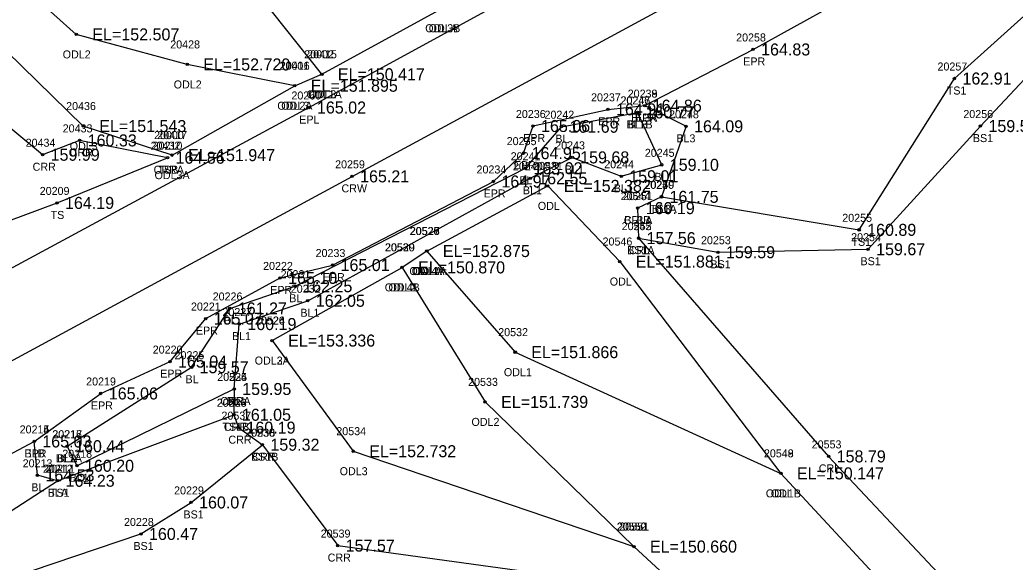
# Model space of a CAD drawing. Extents: x 2279528 to 2280976, y 1061373 to 1062235.
# Drawn here: x 2280192.7 to 2280317.1, y 1061750.3 to 1061818 of the extents above; entities that cross this region are included whole.
import ezdxf

# ---------------------------------------------------------------- set-up
doc = ezdxf.new("R2010")
doc.units = 0
for name, color, linetype in [('RD_DTM_BkLn1', 7, 'Continuous'), ('RD_DTM_BkLn2', 7, 'Continuous'), ('RD_DTM_BkLn_txCode', 7, 'Continuous'), ('RD_EX_H2O', 7, 'Continuous'), ('RD_EX_H2O_txCode', 7, 'Continuous'), ('RD_EX_Road', 7, 'Continuous'), ('RD_EX_Road_txCode', 7, 'Continuous'), ('RD_EX_TX_H2O_ELEV', 7, 'Continuous'), ('RD_EX_TX_Misc_ELEV', 7, 'Continuous'), ('RD_EX_TX_Road_ELEV', 7, 'Continuous'), ('RD_HC_Survey_ELEV', 7, 'Continuous'), ('RD_HC_Survey_txCode', 7, 'Continuous'), ('RD_SMD_Locator', 7, 'Continuous')]:
    doc.layers.add(name, color=color, linetype=linetype)

msp = doc.modelspace()

# ---------------------------------------------------------------- linework, layer by layer
at = {"layer": 'RD_DTM_BkLn1'}
for points in [[(2279559.79, 1061433.13), (2279641.23, 1061477.49), (2279727.93, 1061524.84), (2279814.76, 1061571.75), (2279901.26, 1061618.64), (2279982.8, 1061662.56), (2280064.7, 1061706.86), (2280148.08, 1061751.86), (2280234.22, 1061798.46), (2280310.96, 1061840.01), (2280397.69, 1061887.57), (2280487.27, 1061936.5), (2280573.03, 1061983.12), (2280654.64, 1062027.66), (2280741.28, 1062074.45), (2280833.39, 1062123.87), (2280892.52, 1062155.9), (2280939.46, 1062181.85)], [(2280198.61, 1061764.75), (2280214.16, 1061774.62), (2280218.94, 1061781.96), (2280227.12, 1061784.74), (2280255.88, 1061799.47), (2280260.38, 1061804.66), (2280269.89, 1061806.45)], [(2280198.61, 1061764.75), (2280199.84, 1061762.31), (2280219.49, 1061771.9), (2280220.13, 1061780.01), (2280228.68, 1061782.92), (2280256.48, 1061798.22), (2280261.72, 1061800.83), (2280267.85, 1061798.47), (2280272.92, 1061799.9), (2280269.89, 1061806.45)], [(2280270.78, 1061807.29), (2280275.95, 1061804.71), (2280272.88, 1061795.9), (2280269.9, 1061794.49)], [(2280197.42, 1061760.44), (2280194.9, 1061761.12), (2280194.51, 1061765.35)]]:
    msp.add_lwpolyline(points, dxfattribs=at)
at = {"layer": 'RD_DTM_BkLn2'}
for points in [[(2280272.88, 1061795.9), (2280297.58, 1061791.78), (2280309.49, 1061810.68), (2280320.64, 1061820.76), (2280406.65, 1061872.9), (2280496.79, 1061919.98), (2280582.43, 1061964.41), (2280663.95, 1062011.32), (2280685.25, 1062021.45), (2280750.74, 1062056.04), (2280766.13, 1062062.47), (2280799.22, 1062079.83)], [(2280270.02, 1061790.74), (2280279.94, 1061788.98), (2280298.7, 1061789.36), (2280312.74, 1061804.74), (2280323.13, 1061815.81), (2280411.42, 1061866.03), (2280499.93, 1061915.08), (2280584.56, 1061957.49), (2280666.91, 1062006.18), (2280674.46, 1062011.72), (2280685.18, 1062009.25), (2280689.93, 1062011.32), (2280693.25, 1062019.83), (2280753.26, 1062052.49), (2280766.38, 1062057.83), (2280800.29, 1062072.08)], [(2279918.28, 1061645.97), (2279973.97, 1061675.02), (2280055.41, 1061723.24), (2280139.04, 1061770.27), (2280166.79, 1061783.8), (2280197.35, 1061795.14), (2280211.16, 1061800.79)], [(2280059.22, 1061681.62), (2280071.78, 1061691.76), (2280158.6, 1061733.81), (2280171.38, 1061740.74), (2280178.6, 1061748.25), (2280197.42, 1061760.44), (2280219.45, 1061768.68)], [(2280066.92, 1061680.28), (2280073.37, 1061687.57), (2280161.47, 1061729), (2280173.75, 1061738.9), (2280180.46, 1061744.56), (2280207.84, 1061753.79), (2280214.1, 1061757.73), (2280223.01, 1061764.94)]]:
    msp.add_lwpolyline(points, dxfattribs=at)
at = {"layer": 'RD_EX_H2O'}
for p, q in [((2280230.44, 1061811.21), (2280221.09, 1061822.97)), ((2280243.56, 1061789.13), (2280240.46, 1061787.09))]:
    msp.add_line(p, q, dxfattribs=at)
for points in [[(2280211.16, 1061800.79), (2280200.18, 1061802.95), (2280195.55, 1061801.16), (2280185.62, 1061809.36), (2280166.4, 1061839.27), (2280165.19, 1061847.77), (2280176.13, 1061895.97), (2280173.38, 1061913.11), (2280146.96, 1061940.88), (2280090.97, 1061964.76), (2280049.27, 1062002.4), (2280058.65, 1062048.88), (2280050.78, 1062064.28), (2280035.9, 1062083.09), (2280001.73, 1062095.49), (2279975.65, 1062129.45), (2279976.82, 1062173.44)], [(2280211.72, 1061801.11), (2280200.63, 1061804.74), (2280175.61, 1061829.17), (2280168.33, 1061843.42)], [(2280227.06, 1061809.78), (2280213.62, 1061812.44), (2280199.76, 1061816.19), (2280185.73, 1061828.72), (2280168.33, 1061843.42)], [(2280211.72, 1061801.11), (2280227.06, 1061809.78), (2280230.44, 1061811.21), (2280245.52, 1061819.46)], [(2280243.56, 1061789.13), (2280258.67, 1061797.27), (2280267.66, 1061787.82), (2280287.8, 1061761.36), (2280315.22, 1061731.8), (2280327.48, 1061683.93), (2280307.76, 1061678.04), (2280294.04, 1061661.65), (2280295.74, 1061631.81), (2280310.81, 1061587.94), (2280304.48, 1061546.39), (2280272.84, 1061527.93), (2280259.98, 1061540.36), (2280245.21, 1061537.05), (2280265.99, 1061500.75), (2280299.66, 1061476.28), (2280353.73, 1061471.3), (2280375.17, 1061457.42), (2280376.85, 1061433.19), (2280358.1, 1061419.49), (2280333.32, 1061393.34)], [(2280269.9, 1061794.49), (2280270.02, 1061790.74), (2280293.77, 1061763.48), (2280320.49, 1061735.05), (2280335.4, 1061680.01), (2280309.48, 1061674.63), (2280300.03, 1061660.41), (2280304.47, 1061633.12), (2280315.65, 1061587.64), (2280305.89, 1061543.57), (2280270.77, 1061524.54), (2280257.61, 1061536.28), (2280249.22, 1061535.26), (2280269.33, 1061502.83), (2280301.34, 1061480.02), (2280355.94, 1061475.37), (2280377.91, 1061459.94), (2280379.03, 1061433), (2280360.13, 1061417.18), (2280333.79, 1061387.95)], [(2280243.56, 1061789.13), (2280254.6, 1061776.5), (2280287.8, 1061761.36)], [(2280224.23, 1061777.95), (2280240.46, 1061787.09), (2280250.84, 1061770.29), (2280269.44, 1061752.22)], [(2280224.23, 1061777.95), (2280234.36, 1061764.13), (2280269.44, 1061752.22)], [(2280219.49, 1061771.9), (2280219.45, 1061768.68), (2280220.02, 1061767.07), (2280223.01, 1061764.94), (2280232.42, 1061752.34), (2280266.07, 1061747.74), (2280284.73, 1061725.48), (2280294.86, 1061698.39), (2280278.35, 1061688.54), (2280267.33, 1061659.35), (2280270.69, 1061629.09), (2280284.25, 1061605.42), (2280287.8, 1061578.54), (2280274.54, 1061562.25), (2280261.24, 1061561.71), (2280231.85, 1061561.45), (2280221.24, 1061537.21), (2280230.8, 1061514.2), (2280261.74, 1061476.46), (2280301.47, 1061455.38), (2280325.75, 1061454.26), (2280345.44, 1061445.29), (2280345.67, 1061436.49), (2280313.46, 1061411.55)], [(2280269.44, 1061752.22), (2280294.62, 1061728.95), (2280307.92, 1061693.91), (2280286.99, 1061684.11), (2280274.68, 1061657.45), (2280275.58, 1061630.25), (2280288.86, 1061608.44), (2280293.72, 1061581.7), (2280282.36, 1061552.42), (2280261.54, 1061554.57), (2280239.33, 1061554.65), (2280227, 1061538.36), (2280233.84, 1061514.57), (2280265.76, 1061478.91), (2280302.98, 1061460.15), (2280326.03, 1061460.1), (2280352.94, 1061451.17), (2280354.09, 1061431.94), (2280317.15, 1061398.72)]]:
    msp.add_lwpolyline(points, dxfattribs=at)
at = {"layer": 'RD_EX_Road'}
for points in [[(2279554.31, 1061441.46), (2279636.61, 1061486.51), (2279673.46, 1061506.76), (2279683.06, 1061512.21), (2279723.14, 1061533.54), (2279809.28, 1061580.29), (2279896.91, 1061627.91), (2279977.07, 1061671.02), (2280059.64, 1061715.57), (2280142.91, 1061760.72), (2280228.83, 1061807.06), (2280306.04, 1061849.18), (2280392.98, 1061896.71), (2280482.82, 1061945.75), (2280567.83, 1061991.78), (2280649.94, 1062036.55), (2280660.56, 1062042.19), (2280676.12, 1062050.66), (2280737.28, 1062083.64), (2280828.54, 1062132.77), (2280887.86, 1062164.61), (2280934.91, 1062190.9)], [(2279906, 1061609.76), (2279987.33, 1061653.65), (2280069.09, 1061697.76), (2280153.19, 1061743.35), (2280194.51, 1061765.35), (2280202.82, 1061771.34), (2280211.47, 1061775.32), (2280215.93, 1061780.7), (2280225.22, 1061785.77), (2280231.78, 1061787.38), (2280251.88, 1061797.82), (2280255.66, 1061801.36), (2280256.83, 1061804.75), (2280266.2, 1061806.83), (2280270.78, 1061807.29), (2280284.33, 1061814.31), (2280315.09, 1061831.32), (2280403.05, 1061879.04), (2280492, 1061927.92)]]:
    msp.add_lwpolyline(points, dxfattribs=at)
at = {"layer": 'RD_SMD_Locator'}
for centre in [(2280199.76, 1061816.19), (2280284.33, 1061814.31), (2280213.62, 1061812.44), (2280230.44, 1061811.21), (2280230.44, 1061811.21), (2280227.06, 1061809.78), (2280227.06, 1061809.78), (2280309.49, 1061810.68), (2280270.78, 1061807.29), (2280270.78, 1061807.29), (2280228.83, 1061807.06), (2280266.2, 1061806.83), (2280269.89, 1061806.45), (2280269.89, 1061806.45), (2280200.63, 1061804.74), (2280256.83, 1061804.75), (2280312.74, 1061804.74), (2280260.38, 1061804.66), (2280275.95, 1061804.71), (2280200.18, 1061802.95), (2280195.55, 1061801.16), (2280211.72, 1061801.11), (2280211.72, 1061801.11), (2280255.66, 1061801.36), (2280211.16, 1061800.79), (2280211.16, 1061800.79), (2280261.72, 1061800.83), (2280272.92, 1061799.9), (2280255.88, 1061799.47), (2280234.22, 1061798.46), (2280251.88, 1061797.82), (2280256.48, 1061798.22), (2280258.67, 1061797.27), (2280267.85, 1061798.47), (2280197.35, 1061795.14), (2280272.88, 1061795.9), (2280272.88, 1061795.9), (2280269.9, 1061794.49), (2280269.9, 1061794.49), (2280297.58, 1061791.78), (2280270.02, 1061790.74), (2280270.02, 1061790.74), (2280243.56, 1061789.13), (2280243.56, 1061789.13), (2280243.56, 1061789.13), (2280279.94, 1061788.98), (2280298.7, 1061789.36), (2280231.78, 1061787.38), (2280267.66, 1061787.82), (2280240.46, 1061787.09), (2280240.46, 1061787.09), (2280225.22, 1061785.77), (2280227.12, 1061784.74), (2280228.68, 1061782.92), (2280218.94, 1061781.96), (2280215.93, 1061780.7), (2280220.13, 1061780.01), (2280224.23, 1061777.95), (2280224.23, 1061777.95), (2280254.6, 1061776.5), (2280211.47, 1061775.32), (2280214.16, 1061774.62), (2280202.82, 1061771.34), (2280219.49, 1061771.9), (2280219.49, 1061771.9), (2280250.84, 1061770.29), (2280219.45, 1061768.68), (2280219.45, 1061768.68), (2280220.02, 1061767.07), (2280194.51, 1061765.35), (2280194.51, 1061765.35), (2280223.01, 1061764.94), (2280223.01, 1061764.94), (2280198.61, 1061764.75), (2280198.61, 1061764.75), (2280234.36, 1061764.13), (2280293.77, 1061763.48), (2280199.84, 1061762.31), (2280287.8, 1061761.36), (2280287.8, 1061761.36), (2280194.9, 1061761.12), (2280197.42, 1061760.44), (2280197.42, 1061760.44), (2280214.1, 1061757.73), (2280207.84, 1061753.79), (2280232.42, 1061752.34), (2280269.44, 1061752.22), (2280269.44, 1061752.22), (2280269.44, 1061752.22)]:
    msp.add_circle(centre, 0.15, dxfattribs=at)

# ---------------------------------------------------------------- texts
at = {"layer": 'RD_DTM_BkLn_txCode'}
for s, p in [('20257', (2280307.37, 1061811.68)), ('20239', (2280268.66, 1061808.29)), ('TS1', (2280308.53, 1061808.68)), ('20246', (2280267.75, 1061807.45)), ('20247', (2280267.77, 1061807.45)), ('20242', (2280258.26, 1061805.66)), ('BL3A', (2280269.09, 1061805.29)), ('20248', (2280273.83, 1061805.71)), ('20256', (2280310.6, 1061805.74)), ('BL1B', (2280268.5, 1061804.45)), ('BLB', (2280268.66, 1061804.45)), ('BL', (2280259.62, 1061802.66)), ('BL3', (2280274.74, 1061802.71)), ('BS1', (2280311.79, 1061802.74)), ('20210', (2280209.29, 1061801.79)), ('20243', (2280259.6, 1061801.83)), ('20241', (2280254.04, 1061800.47)), ('20245', (2280270.8, 1061800.9)), ('20240', (2280254.32, 1061799.22)), ('20244', (2280265.73, 1061799.47)), ('TSB', (2280209.9, 1061798.79)), ('BL1', (2280260.8, 1061798.83)), ('BL1', (2280272, 1061797.9)), ('BL', (2280255.12, 1061797.47)), ('BL1', (2280266.92, 1061796.47)), ('20250', (2280270.73, 1061796.9)), ('20249', (2280270.77, 1061796.9)), ('20209', (2280195.19, 1061796.14)), ('BL1', (2280255.56, 1061796.22)), ('20251', (2280268.07, 1061795.49)), ('TS', (2280196.55, 1061793.14)), ('TS1A', (2280271.44, 1061793.9)), ('BL3', (2280271.68, 1061793.9)), ('20255', (2280295.47, 1061792.78)), ('20252', (2280267.91, 1061791.74)), ('BL3B', (2280268.22, 1061792.49)), ('20254', (2280296.58, 1061790.36)), ('20253', (2280277.82, 1061789.98)), ('TS1', (2280296.62, 1061789.78)), ('BS1A', (2280268.59, 1061788.74)), ('BS1', (2280279, 1061786.98)), ('BS1', (2280297.75, 1061787.36)), ('20231', (2280225.29, 1061785.74)), ('20226', (2280216.8, 1061782.96)), ('BL', (2280226.37, 1061782.74)), ('20232', (2280226.56, 1061783.92)), ('20227', (2280218.02, 1061781.01)), ('BL1', (2280227.76, 1061780.92)), ('BL', (2280218.18, 1061779.96)), ('BL1', (2280219.21, 1061778.01)), ('20225', (2280212.04, 1061775.62)), ('20224', (2280217.37, 1061772.9)), ('BL', (2280213.41, 1061772.62)), ('20223', (2280217.33, 1061769.68)), ('BL1', (2280218.56, 1061769.9)), ('TS1B', (2280218.02, 1061766.68)), ('20214', (2280192.68, 1061766.35)), ('20216', (2280196.75, 1061765.75)), ('20217', (2280196.77, 1061765.75)), ('20230', (2280220.85, 1061765.94)), ('BLB', (2280193.29, 1061763.35)), ('20218', (2280198.01, 1061763.31)), ('BS1B', (2280221.59, 1061762.94)), ('20213', (2280193.06, 1061762.12)), ('BL1A', (2280197.2, 1061762.75)), ('BLA', (2280197.36, 1061762.75)), ('20212', (2280195.59, 1061761.44)), ('20211', (2280195.87, 1061761.44)), ('BL', (2280194.14, 1061759.12)), ('BL1', (2280198.92, 1061760.31)), ('BLA', (2280196.18, 1061758.44)), ('TS1', (2280196.46, 1061758.44)), ('20229', (2280211.98, 1061758.73)), ('BS1', (2280213.15, 1061755.73)), ('20228', (2280205.72, 1061754.79)), ('BS1', (2280206.9, 1061751.79))]:
    msp.add_text(s, height=1, dxfattribs=at).set_placement(p)
at = {"layer": 'RD_EX_H2O_txCode'}
for s, p in [('ODL3B', (2280243.36, 1061816.46)), ('ODLA', (2280243.79, 1061816.46)), ('20428', (2280211.5, 1061814.44)), ('ODL2', (2280198.06, 1061813.19)), ('20002', (2280228.24, 1061813.21)), ('20415', (2280228.61, 1061813.21)), ('20001', (2280225.15, 1061811.78)), ('20416', (2280225.2, 1061811.78)), ('ODL2', (2280211.93, 1061809.44)), ('ODL1A', (2280228.54, 1061808.21)), ('ODL3', (2280228.75, 1061808.21)), ('20436', (2280198.49, 1061806.74)), ('ODL2A', (2280224.88, 1061806.78)), ('ODL3', (2280225.37, 1061806.78)), ('20433', (2280198.06, 1061803.95)), ('20000', (2280209.48, 1061803.11)), ('20417', (2280209.88, 1061803.11)), ('20434', (2280193.43, 1061802.16)), ('ODL3', (2280198.94, 1061801.74)), ('20432', (2280209.04, 1061801.79)), ('CRR', (2280198.93, 1061800.95)), ('CRR', (2280194.3, 1061799.16)), ('20531', (2280256.83, 1061799.27)), ('CRRA', (2280209.42, 1061798.79)), ('ODL3A', (2280209.54, 1061798.11)), ('ODL3A', (2280209.54, 1061798.11)), ('20544', (2280267.78, 1061795.49)), ('ODL', (2280257.43, 1061794.27)), ('20545', (2280267.91, 1061791.74)), ('CRLA', (2280268.18, 1061792.49)), ('20520', (2280241.41, 1061791.13)), ('20527', (2280241.45, 1061791.13)), ('20528', (2280241.45, 1061791.13)), ('20530', (2280238.31, 1061789.09)), ('20529', (2280238.35, 1061789.09)), ('20546', (2280265.52, 1061789.82)), ('CRL', (2280268.8, 1061788.74)), ('ODL4A', (2280241.38, 1061786.13)), ('ODL1A', (2280241.67, 1061786.13)), ('ODLA', (2280241.83, 1061786.13)), ('ODL4B', (2280238.3, 1061784.09)), ('ODL2', (2280238.77, 1061784.09)), ('ODL', (2280266.42, 1061784.82)), ('20526', (2280222.08, 1061779.95)), ('20524', (2280222.11, 1061779.95)), ('20532', (2280252.48, 1061778.5)), ('ODL2A', (2280222.05, 1061774.95)), ('ODL3A', (2280222.05, 1061774.95)), ('20535', (2280217.37, 1061772.9)), ('ODL1', (2280253.19, 1061773.5)), ('20533', (2280248.72, 1061772.29)), ('20536', (2280217.31, 1061769.68)), ('CRRA', (2280217.75, 1061769.9)), ('20537', (2280217.9, 1061768.07)), ('CRR', (2280218.2, 1061766.68)), ('ODL2', (2280249.14, 1061767.29)), ('20538', (2280220.89, 1061765.94)), ('20534', (2280232.25, 1061766.13)), ('CRR', (2280218.77, 1061765.07)), ('20553', (2280291.65, 1061764.48)), ('CRR', (2280221.76, 1061762.94)), ('20548', (2280285.68, 1061763.36)), ('20549', (2280285.68, 1061763.36)), ('ODL3', (2280232.67, 1061761.13)), ('CRL', (2280292.54, 1061761.48)), ('ODL1B', (2280285.92, 1061758.36)), ('ODL', (2280286.55, 1061758.36)), ('20550', (2280267.29, 1061754.22)), ('20552', (2280267.33, 1061754.22)), ('20551', (2280267.61, 1061754.22)), ('20539', (2280230.3, 1061753.34)), ('CRR', (2280231.17, 1061750.34))]:
    msp.add_text(s, height=1, dxfattribs=at).set_placement(p)
at = {"layer": 'RD_EX_Road_txCode'}
for s, p in [('20258', (2280282.21, 1061815.31)), ('EPR', (2280283.1, 1061812.31)), ('20260', (2280226.64, 1061808.06)), ('20237', (2280264.08, 1061807.83)), ('20238', (2280268.66, 1061808.29)), ('20236', (2280254.69, 1061805.75)), ('EPR', (2280269.55, 1061805.29)), ('EPL', (2280227.62, 1061805.06)), ('EPR', (2280264.97, 1061804.83)), ('EPR', (2280255.6, 1061802.75)), ('20235', (2280253.54, 1061802.36)), ('EPR', (2280254.43, 1061799.36)), ('20234', (2280249.77, 1061798.82)), ('EPR', (2280250.66, 1061795.82)), ('20233', (2280229.66, 1061788.38)), ('20222', (2280223.1, 1061786.77)), ('EPR', (2280230.55, 1061785.38)), ('EPR', (2280223.99, 1061783.77)), ('20221', (2280214.09, 1061781.7)), ('EPR', (2280214.7, 1061778.7)), ('20220', (2280209.31, 1061776.32)), ('EPR', (2280210.24, 1061773.32)), ('20219', (2280200.99, 1061772.34)), ('EPR', (2280201.59, 1061769.34)), ('20215', (2280192.68, 1061766.35)), ('EPR', (2280193.29, 1061763.35))]:
    msp.add_text(s, height=1, dxfattribs=at).set_placement(p)
at = {"layer": 'RD_EX_TX_H2O_ELEV'}
for s, p in [('EL=152.507', (2280201.76, 1061815.44)), ('EL=152.720', (2280215.62, 1061811.69)), ('EL=150.417', (2280232.44, 1061810.46)), ('EL=150.417', (2280232.44, 1061810.46)), ('EL=151.895', (2280229.06, 1061809.03)), ('EL=151.895', (2280229.06, 1061809.03)), ('EL=151.543', (2280202.63, 1061803.99)), ('160.33', (2280201.18, 1061802.2)), ('159.99', (2280196.55, 1061800.41)), ('164.86', (2280212.16, 1061800.04)), ('EL=151.947', (2280213.72, 1061800.36)), ('EL=151.947', (2280213.72, 1061800.36)), ('EL=152.382', (2280260.67, 1061796.52)), ('160.19', (2280270.9, 1061793.74)), ('157.56', (2280271.02, 1061789.99)), ('EL=152.875', (2280245.56, 1061788.38)), ('EL=152.875', (2280245.56, 1061788.38)), ('EL=152.875', (2280245.56, 1061788.38)), ('EL=150.870', (2280242.46, 1061786.34)), ('EL=150.870', (2280242.46, 1061786.34)), ('EL=151.881', (2280269.66, 1061787.07)), ('EL=153.336', (2280226.23, 1061777.2)), ('EL=153.336', (2280226.23, 1061777.2)), ('EL=151.866', (2280256.6, 1061775.75)), ('159.95', (2280220.49, 1061771.15)), ('EL=151.739', (2280252.84, 1061769.54)), ('161.05', (2280220.45, 1061767.93)), ('160.19', (2280221.02, 1061766.32)), ('159.32', (2280224.01, 1061764.19)), ('EL=152.732', (2280236.36, 1061763.38)), ('158.79', (2280294.77, 1061762.73)), ('EL=150.147', (2280289.8, 1061760.61)), ('EL=150.147', (2280289.8, 1061760.61)), ('157.57', (2280233.42, 1061751.59)), ('EL=150.660', (2280271.44, 1061751.47)), ('EL=150.660', (2280271.44, 1061751.47)), ('EL=150.660', (2280271.44, 1061751.47))]:
    msp.add_text(s, height=1.5, dxfattribs=at).set_placement(p)
at = {"layer": 'RD_EX_TX_Misc_ELEV'}
for s, p in [('162.91', (2280310.49, 1061809.93)), ('164.86', (2280271.78, 1061806.54)), ('160.77', (2280270.89, 1061805.7)), ('160.77', (2280270.89, 1061805.7)), ('161.69', (2280261.38, 1061803.91)), ('164.09', (2280276.95, 1061803.96)), ('159.56', (2280313.74, 1061803.99)), ('164.86', (2280212.16, 1061800.04)), ('159.68', (2280262.72, 1061800.08)), ('163.02', (2280256.88, 1061798.72)), ('159.10', (2280273.92, 1061799.15)), ('162.55', (2280257.48, 1061797.47)), ('159.01', (2280268.85, 1061797.72)), ('161.75', (2280273.88, 1061795.15)), ('161.75', (2280273.88, 1061795.15)), ('164.19', (2280198.35, 1061794.39)), ('160.19', (2280270.9, 1061793.74)), ('160.89', (2280298.58, 1061791.03)), ('157.56', (2280271.02, 1061789.99)), ('159.67', (2280299.7, 1061788.61)), ('159.59', (2280280.94, 1061788.23)), ('162.25', (2280228.12, 1061783.99)), ('161.27', (2280219.94, 1061781.21)), ('162.05', (2280229.68, 1061782.17)), ('160.19', (2280221.13, 1061779.26)), ('159.57', (2280215.16, 1061773.87)), ('159.95', (2280220.49, 1061771.15)), ('161.05', (2280220.45, 1061767.93)), ('165.03', (2280195.51, 1061764.6)), ('160.44', (2280199.61, 1061764)), ('160.44', (2280199.61, 1061764)), ('159.32', (2280224.01, 1061764.19)), ('160.20', (2280200.84, 1061761.56)), ('164.53', (2280195.9, 1061760.37)), ('164.23', (2280198.42, 1061759.69)), ('164.23', (2280198.42, 1061759.69)), ('160.07', (2280215.1, 1061756.98)), ('160.47', (2280208.84, 1061753.04))]:
    msp.add_text(s, height=1.5, dxfattribs=at).set_placement(p)
at = {"layer": 'RD_EX_TX_Road_ELEV'}
for s, p in [('164.83', (2280285.33, 1061813.56)), ('165.02', (2280229.83, 1061806.31)), ('164.91', (2280267.2, 1061806.08)), ('164.86', (2280271.78, 1061806.54)), ('165.06', (2280257.83, 1061804)), ('164.95', (2280256.66, 1061800.61)), ('164.97', (2280252.88, 1061797.07)), ('165.01', (2280232.78, 1061786.63)), ('165.10', (2280226.22, 1061785.02)), ('165.07', (2280216.93, 1061779.95)), ('165.04', (2280212.47, 1061774.57)), ('165.06', (2280203.82, 1061770.59)), ('165.03', (2280195.51, 1061764.6))]:
    msp.add_text(s, height=1.5, dxfattribs=at).set_placement(p)
at = {"layer": 'RD_HC_Survey_ELEV'}
msp.add_text('165.21', height=1.5, dxfattribs=at).set_placement((2280235.22, 1061797.71))
at = {"layer": 'RD_HC_Survey_txCode'}
for s, p in [('20259', (2280232.1, 1061799.46)), ('CRW', (2280232.9, 1061796.46))]:
    msp.add_text(s, height=1, dxfattribs=at).set_placement(p)

doc.saveas('drawing.dxf')
